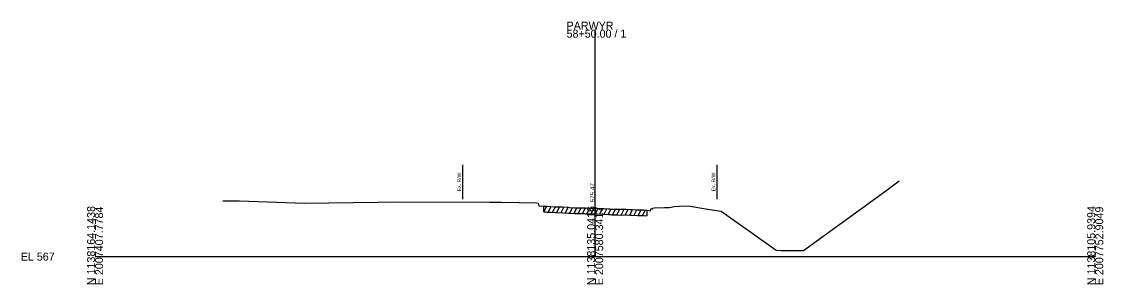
# Model space of a CAD drawing. Extents: x -2173 to 2007764, y -181 to 1138563.
# Drawn here: x 1017.4 to 1395.9, y 3990.3 to 4082.2 of the extents above; entities that cross this region are included whole.
import ezdxf

# ---------------------------------------------------------------- set-up
doc = ezdxf.new("R2010")
doc.units = 0
for name, color, linetype in [('Default', 7, 'Continuous'), ('RD_PD_Final_TrvlWay', 7, 'Continuous'), ('RD_PD_MedBWall', 7, 'Continuous'), ('RD_XS_ExPaveRet', 7, 'Continuous'), ('RD_XS_ExRW', 7, 'Continuous'), ('RD_XS_TX_Elev_EX', 7, 'Continuous')]:
    doc.layers.add(name, color=color, linetype=linetype)

msp = doc.modelspace()

# ---------------------------------------------------------------- linework, layer by layer
at = {"layer": 'RD_PD_Final_TrvlWay'}
msp.add_lwpolyline([(1087.79, 4019.53), (1093.67, 4019.56), (1116.44, 4018.66), (1141.94, 4019.05), (1149, 4019.13), (1181.22, 4019.01), (1183.17, 4019.03), (1185.33, 4019.01), (1197.7, 4018.8), (1198.11, 4018.74), (1198.38, 4017.76), (1200.2, 4017.62), (1200.66, 4017.62), (1201.17, 4017.6), (1202.54, 4017.56), (1204.22, 4017.46), (1204.57, 4017.44), (1206.66, 4017.36), (1208.63, 4017.24), (1209.09, 4017.21), (1210.98, 4017.08), (1211.89, 4017.05), (1212.57, 4017.05), (1214.33, 4017.02), (1214.71, 4017.01), (1216.41, 4017), (1216.74, 4017), (1218.35, 4016.94), (1218.85, 4016.92), (1220.8, 4016.83), (1221.29, 4016.8), (1222.83, 4016.72), (1223.41, 4016.67), (1223.95, 4016.64), (1224.62, 4016.64), (1226.01, 4016.59), (1226.88, 4016.55), (1228.91, 4016.56), (1230.38, 4016.53), (1231.05, 4016.51), (1232.97, 4016.39), (1234.33, 4016.39), (1235.18, 4016.36), (1236.2, 4016.28), (1237.52, 4016.01), (1237.63, 4016.75), (1238.14, 4016.71), (1238.19, 4016.97), (1238.73, 4017.02), (1242.31, 4017.14), (1243.68, 4017.17), (1244.08, 4017.21), (1245.75, 4017.56), (1247.59, 4017.68), (1250.64, 4017.8), (1257.55, 4016.63), (1262.18, 4015.84), (1278.17, 4004.61), (1281.45, 4002.2), (1283.1, 4002.18), (1291.03, 4002.1), (1319.8, 4023.03), (1324.46, 4026.45)], dxfattribs=at)
at = {"layer": 'RD_PD_MedBWall'}
for p, q in [((1218.1, 4000), (1218.1, 4079.35)), ((1043.1, 4000), (1218.1, 4000)), ((1218.1, 4000), (1393.1, 4000))]:
    msp.add_line(p, q, dxfattribs=at)
at = {"layer": 'RD_XS_ExPaveRet'}
for p, q in [((1200.2, 4015.62), (1200.2, 4017.62)), ((1200.2, 4015.62), (1201.19, 4017.6)), ((1201.7, 4015.58), (1202.69, 4017.55)), ((1203.2, 4015.52), (1204.18, 4017.46)), ((1204.7, 4015.44), (1205.68, 4017.4)), ((1206.2, 4015.38), (1207.18, 4017.33)), ((1207.7, 4015.3), (1208.68, 4017.24)), ((1209.2, 4015.2), (1210.17, 4017.13)), ((1210.7, 4015.1), (1211.68, 4017.05)), ((1212.2, 4015.05), (1213.2, 4017.04)), ((1213.7, 4015.03), (1214.7, 4017.01)), ((1215.2, 4015.01), (1216.2, 4017)), ((1216.7, 4015), (1217.69, 4016.96)), ((1218.2, 4014.94), (1219.18, 4016.9)), ((1219.7, 4014.88), (1220.68, 4016.83)), ((1221.2, 4014.8), (1222.18, 4016.75)), ((1222.7, 4014.73), (1223.67, 4016.66)), ((1224.2, 4014.64), (1225.19, 4016.62)), ((1225.7, 4014.6), (1226.68, 4016.56)), ((1227.2, 4014.55), (1228.2, 4016.55)), ((1228.7, 4014.56), (1229.7, 4016.54)), ((1230.2, 4014.53), (1231.19, 4016.51)), ((1231.7, 4014.47), (1232.67, 4016.41)), ((1233.2, 4014.39), (1234.21, 4016.39)), ((1234.7, 4014.38), (1235.68, 4016.33)), ((1236.2, 4016.28), (1236.2, 4014.28)), ((1200.2, 4015.62), (1200.66, 4015.62)), ((1200.66, 4015.62), (1201.17, 4015.6)), ((1201.17, 4015.6), (1202.54, 4015.56)), ((1202.54, 4015.56), (1204.22, 4015.46)), ((1204.22, 4015.46), (1204.57, 4015.44)), ((1204.57, 4015.44), (1206.66, 4015.36)), ((1206.66, 4015.36), (1208.63, 4015.24)), ((1208.63, 4015.24), (1209.09, 4015.21)), ((1209.09, 4015.21), (1210.98, 4015.08)), ((1210.98, 4015.08), (1211.89, 4015.05)), ((1211.89, 4015.05), (1212.57, 4015.05)), ((1212.57, 4015.05), (1214.33, 4015.02)), ((1214.33, 4015.02), (1214.71, 4015.01)), ((1214.71, 4015.01), (1216.41, 4015)), ((1216.41, 4015), (1216.74, 4015)), ((1216.74, 4015), (1218.35, 4014.94)), ((1218.35, 4014.94), (1218.85, 4014.92)), ((1218.85, 4014.92), (1220.8, 4014.83)), ((1220.8, 4014.83), (1221.29, 4014.8)), ((1221.29, 4014.8), (1222.83, 4014.72)), ((1222.83, 4014.72), (1223.41, 4014.67)), ((1223.41, 4014.67), (1223.95, 4014.64)), ((1223.95, 4014.64), (1224.62, 4014.64)), ((1224.62, 4014.64), (1226.01, 4014.59)), ((1226.01, 4014.59), (1226.88, 4014.55)), ((1226.88, 4014.55), (1228.91, 4014.56)), ((1228.91, 4014.56), (1230.38, 4014.53)), ((1230.38, 4014.53), (1231.05, 4014.51)), ((1231.05, 4014.51), (1232.97, 4014.39)), ((1232.97, 4014.39), (1234.33, 4014.39)), ((1234.33, 4014.39), (1235.18, 4014.36)), ((1235.18, 4014.36), (1236.2, 4014.28))]:
    msp.add_line(p, q, dxfattribs=at)
at = {"layer": 'RD_XS_ExRW'}
for p, q in [((1171.67, 4032.04), (1171.67, 4020.04)), ((1260.66, 4032.04), (1260.66, 4020.04))]:
    msp.add_line(p, q, dxfattribs=at)

# ---------------------------------------------------------------- texts
at = {"layer": 'Default'}
msp.add_text('-', height=0.0001, dxfattribs=at).set_placement((1043.1, 4000))
at = {"layer": 'RD_PD_MedBWall'}
for s, p in [('PARWYR', (1208.1, 4079.35)), ('58+50.00 / 1', (1208.1, 4076.55)), ('EL 567', (1017.1, 3998.6))]:
    msp.add_text(s, height=2.8, dxfattribs=at).set_placement(p)
for s, p in [('N 1138164.1438', (1043.1, 3990)), ('E 2007407.7784', (1045.9, 3990)), ('N 1138135.0416', (1218.1, 3990)), ('E 2007580.3417', (1220.9, 3990)), ('N 1138105.9394', (1393.1, 3990)), ('E 2007752.9049', (1395.9, 3990))]:
    msp.add_text(s, height=2.8, rotation=90, dxfattribs=at).set_placement(p)
at = {"layer": 'RD_XS_ExRW'}
for p in [(1171.17, 4022.81), (1260.16, 4022.81)]:
    msp.add_text('Ex. R/W ', height=1.3, rotation=90, dxfattribs=at).set_placement(p)
at = {"layer": 'RD_XS_TX_Elev_EX'}
msp.add_text('575.47', height=1.6, rotation=90, dxfattribs=at).set_placement((1218, 4018.95))

doc.saveas('drawing.dxf')
